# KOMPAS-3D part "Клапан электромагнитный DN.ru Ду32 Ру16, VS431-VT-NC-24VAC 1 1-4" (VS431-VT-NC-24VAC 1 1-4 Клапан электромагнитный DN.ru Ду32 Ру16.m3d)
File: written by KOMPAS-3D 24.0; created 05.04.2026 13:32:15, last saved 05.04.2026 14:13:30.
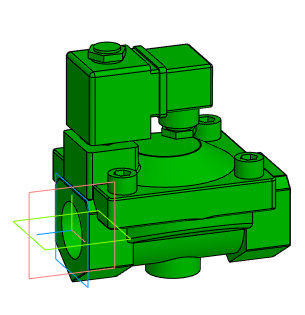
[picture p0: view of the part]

Document properties: Автор: artio; Полное имя файла: C:\Users\artio\OneDrive\Рабочий стол\Клапан электромагнитный DN.ru\VS431\VS431-VT-NC\VS431-VT-NC-24VAC\Ду32\VS431-VT-NC-24VAC 1 1-4 Клапан электромагнитный DN.ru Ду32 Ру16.m3d

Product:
- Body: Тело 1  | qty 1
    Масса: 3.709873
- Part/product: Клапан электромагнитный DN.ru Ду32 Ру16  | designation VS431-VT-NC-24VAC 1 1-4
    Масса: 1.701
    Раздел спецификации: Прочие изделия
    Примечание: D130-05515
    additional columns: ef56311e-7521-43dc-8291-0e6108b3d81d; artio; c; Шероховатость не задана; Да

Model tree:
1. Операция без истории:1

Expressions: VS431-VT-NC-24VAC 1 1-4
